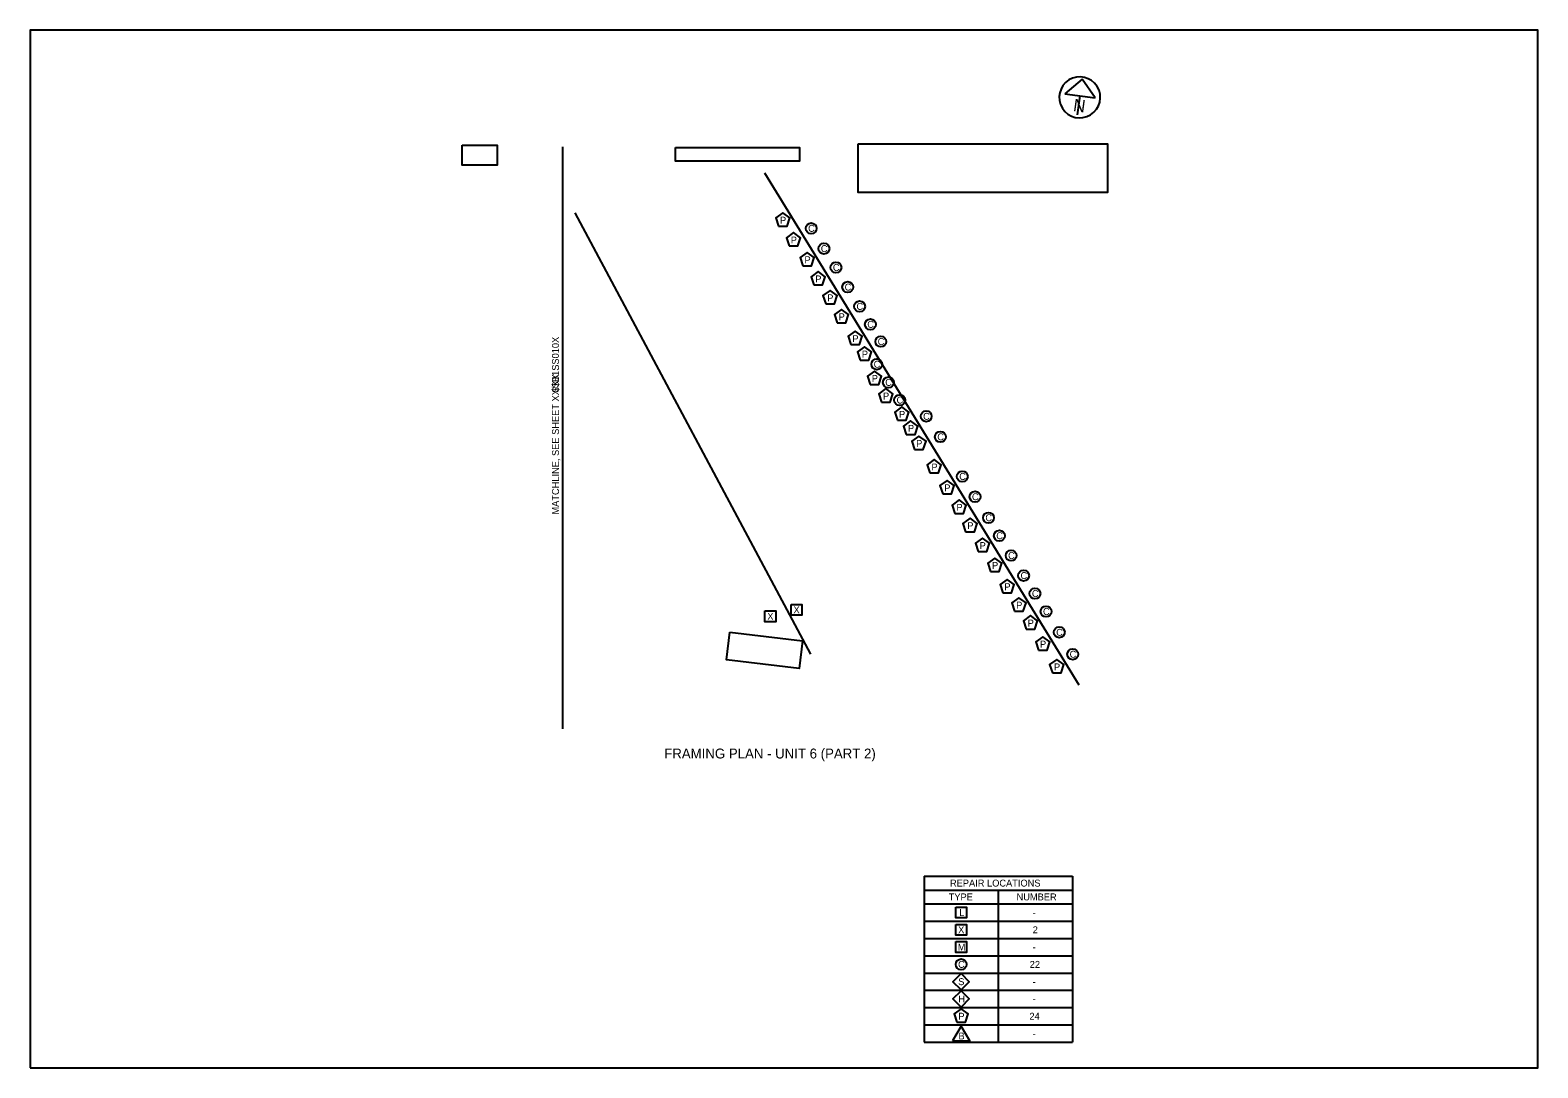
# Model space of a CAD drawing. Extents: x 100 to 130.5, y 100 to 121.
import ezdxf

# ---------------------------------------------------------------- set-up
doc = ezdxf.new("R2010")
doc.units = 0
for name, color, linetype in [('BR_P_Gen_Text', 7, 'Continuous'), ('BR_X_Sub_Centerline', 7, 'Continuous'), ('BR_X_Sub_Text', 7, 'Continuous'), ('SC_Scratch1', 7, 'Continuous'), ('SH_Data', 7, 'Continuous'), ('SH_Masking', 7, 'Continuous')]:
    doc.layers.add(name, color=color, linetype=linetype)

msp = doc.modelspace()

# ---------------------------------------------------------------- linework, layer by layer
at = {"layer": 'BR_P_Gen_Text'}
for p, q in [((110.767, 118.639), (110.767, 106.861)), ((118.083, 103.879), (118.083, 100.519)), ((118.083, 103.879), (121.083, 103.879)), ((121.083, 103.879), (121.083, 100.519)), ((118.083, 103.599), (121.083, 103.599)), ((119.583, 103.599), (119.583, 100.519)), ((118.083, 103.319), (121.083, 103.319)), ((118.083, 102.969), (121.083, 102.969)), ((118.083, 102.619), (121.083, 102.619)), ((118.083, 102.269), (121.083, 102.269)), ((118.083, 101.919), (121.083, 101.919)), ((118.083, 101.569), (121.083, 101.569)), ((118.083, 101.219), (121.083, 101.219)), ((118.083, 100.869), (121.083, 100.869)), ((118.083, 100.519), (121.083, 100.519))]:
    msp.add_line(p, q, dxfattribs=at)
for points in [[(115.136, 117.033), (115.312, 117.033), (115.367, 117.201), (115.224, 117.304), (115.082, 117.201)], [(115.355, 116.632), (115.531, 116.632), (115.586, 116.8), (115.443, 116.903), (115.3, 116.8)], [(115.633, 116.231), (115.809, 116.231), (115.863, 116.399), (115.721, 116.502), (115.578, 116.399)], [(115.851, 115.844), (116.028, 115.844), (116.082, 116.011), (115.939, 116.115), (115.797, 116.011)], [(116.093, 115.461), (116.269, 115.461), (116.323, 115.628), (116.181, 115.732), (116.038, 115.628)], [(116.323, 115.078), (116.5, 115.078), (116.554, 115.246), (116.412, 115.349), (116.269, 115.246)], [(116.601, 114.636), (116.778, 114.636), (116.832, 114.804), (116.689, 114.907), (116.547, 114.804)], [(116.793, 114.322), (116.969, 114.322), (117.023, 114.489), (116.881, 114.593), (116.738, 114.489)], [(116.993, 113.829), (117.169, 113.829), (117.224, 113.997), (117.081, 114.101), (116.939, 113.997)], [(117.221, 113.474), (117.397, 113.474), (117.452, 113.642), (117.309, 113.745), (117.166, 113.642)], [(117.544, 113.105), (117.721, 113.105), (117.775, 113.272), (117.632, 113.376), (117.49, 113.272)], [(117.724, 112.82), (117.901, 112.82), (117.955, 112.988), (117.812, 113.092), (117.67, 112.988)], [(117.892, 112.514), (118.068, 112.514), (118.123, 112.682), (117.98, 112.785), (117.837, 112.682)], [(118.201, 112.038), (118.377, 112.038), (118.432, 112.206), (118.289, 112.309), (118.146, 112.206)], [(118.46, 111.616), (118.636, 111.616), (118.691, 111.783), (118.548, 111.887), (118.405, 111.783)], [(118.707, 111.221), (118.883, 111.221), (118.938, 111.389), (118.795, 111.493), (118.653, 111.389)], [(118.925, 110.85), (119.101, 110.85), (119.156, 111.018), (119.013, 111.122), (118.87, 111.018)], [(119.176, 110.448), (119.352, 110.448), (119.406, 110.616), (119.264, 110.719), (119.121, 110.616)], [(119.426, 110.045), (119.603, 110.045), (119.657, 110.213), (119.514, 110.317), (119.372, 110.213)], [(119.676, 109.615), (119.852, 109.615), (119.907, 109.783), (119.764, 109.886), (119.622, 109.783)], [(119.915, 109.241), (120.091, 109.241), (120.146, 109.409), (120.003, 109.513), (119.861, 109.409)], [(114.863, 109.247), (115.083, 109.247), (115.083, 109.027), (114.863, 109.027)], [(115.393, 109.379), (115.613, 109.379), (115.613, 109.159), (115.393, 109.159)], [(120.148, 108.88), (120.325, 108.88), (120.379, 109.048), (120.237, 109.151), (120.094, 109.048)], [(120.396, 108.454), (120.572, 108.454), (120.627, 108.622), (120.484, 108.725), (120.342, 108.622)], [(120.679, 107.993), (120.855, 107.993), (120.91, 108.161), (120.767, 108.264), (120.624, 108.161)], [(118.723, 103.254), (118.943, 103.254), (118.943, 103.034), (118.723, 103.034)], [(118.723, 102.904), (118.943, 102.904), (118.943, 102.684), (118.723, 102.684)], [(118.723, 102.554), (118.943, 102.554), (118.943, 102.334), (118.723, 102.334)], [(118.833, 101.909), (118.998, 101.744), (118.833, 101.579), (118.668, 101.744)], [(118.833, 101.559), (118.998, 101.394), (118.833, 101.229), (118.668, 101.394)], [(118.745, 100.923), (118.922, 100.923), (118.976, 101.091), (118.833, 101.194), (118.691, 101.091)], [(118.66, 100.544), (119.007, 100.544), (118.833, 100.844)]]:
    msp.add_lwpolyline(points, close=True, dxfattribs=at)
for centre in [(115.8, 116.989), (116.058, 116.579), (116.301, 116.197), (116.54, 115.8), (116.779, 115.409), (116.998, 115.046), (117.208, 114.698), (117.127, 114.239), (117.361, 113.872), (117.59, 113.513), (118.127, 113.185), (118.414, 112.77), (118.857, 111.968), (119.115, 111.557), (119.387, 111.132), (119.607, 110.769), (119.845, 110.368), (120.098, 109.962), (120.327, 109.599), (120.552, 109.235), (120.819, 108.814), (121.091, 108.37), (118.833, 102.094)]:
    msp.add_circle(centre, 0.11, dxfattribs=at)
at = {"layer": 'BR_X_Sub_Centerline'}
for p, q in [((121.22, 107.746), (114.862, 118.106)), ((115.795, 108.373), (111.025, 117.306))]:
    msp.add_line(p, q, dxfattribs=at)
at = {"layer": 'BR_X_Sub_Text'}
for points in [[(113.054, 118.628), (115.565, 118.628), (115.565, 118.347), (113.054, 118.347)], [(114.152, 108.817), (115.625, 108.64), (115.558, 108.081), (114.085, 108.258)]]:
    msp.add_lwpolyline(points, close=True, dxfattribs=at)
at = {"layer": 'SC_Scratch1'}
msp.add_lwpolyline([(100, 100), (130.5, 100), (130.5, 121), (100, 121)], close=True, dxfattribs=at)
at = {"layer": 'SH_Data'}
for p, q in [((121.284, 120.009), (120.932, 119.713)), ((121.542, 119.629), (121.284, 120.009)), ((120.932, 119.713), (121.542, 119.629)), ((121.237, 119.671), (121.184, 119.288))]:
    msp.add_line(p, q, dxfattribs=at)
msp.add_arc((121.233, 119.639), 0.415, 121.8974, 121.8808, dxfattribs=at)
at = {"layer": 'SH_Masking'}
for points in [[(108.741, 118.671), (109.447, 118.671), (109.447, 118.265), (108.741, 118.265)], [(116.753, 118.697), (121.793, 118.697), (121.793, 117.714), (116.753, 117.714)]]:
    msp.add_lwpolyline(points, close=True, dxfattribs=at)

# ---------------------------------------------------------------- texts
at = {"layer": 'BR_P_Gen_Text'}
for s, height, p in [('P', 0.14, (115.168, 117.084)), ('P', 0.14, (115.387, 116.683)), ('C', 0.14, (115.738, 116.919)), ('C', 0.14, (115.995, 116.509)), ('P', 0.14, (115.665, 116.282)), ('C', 0.14, (116.239, 116.127)), ('P', 0.14, (115.883, 115.895)), ('P', 0.14, (116.125, 115.512)), ('C', 0.14, (116.477, 115.73)), ('C', 0.14, (116.716, 115.339)), ('P', 0.14, (116.355, 115.129)), ('C', 0.14, (116.935, 114.976)), ('P', 0.14, (116.633, 114.687)), ('C', 0.14, (117.145, 114.628)), ('P', 0.14, (116.825, 114.373)), ('C', 0.14, (117.064, 114.169)), ('P', 0.14, (117.025, 113.881)), ('C', 0.14, (117.298, 113.802)), ('P', 0.14, (117.253, 113.525)), ('C', 0.14, (117.527, 113.443)), ('P', 0.14, (117.576, 113.156)), ('C', 0.14, (118.064, 113.115)), ('P', 0.14, (117.756, 112.872)), ('P', 0.14, (117.924, 112.565)), ('C', 0.14, (118.351, 112.7)), ('P', 0.14, (118.233, 112.089)), ('C', 0.14, (118.795, 111.898)), ('P', 0.14, (118.492, 111.667)), ('P', 0.14, (118.739, 111.273)), ('C', 0.14, (119.052, 111.487)), ('P', 0.14, (118.957, 110.902)), ('C', 0.14, (119.324, 111.062)), ('C', 0.14, (119.544, 110.699)), ('P', 0.14, (119.207, 110.499)), ('C', 0.14, (119.783, 110.298)), ('P', 0.14, (119.458, 110.097)), ('P', 0.14, (119.708, 109.666)), ('C', 0.14, (120.035, 109.892)), ('C', 0.14, (120.265, 109.529)), ('X', 0.14, (114.912, 109.067)), ('X', 0.14, (115.442, 109.199)), ('P', 0.14, (119.947, 109.293)), ('C', 0.14, (120.489, 109.165)), ('P', 0.14, (120.18, 108.931)), ('C', 0.14, (120.756, 108.744)), ('P', 0.14, (120.428, 108.505)), ('C', 0.14, (121.028, 108.3)), ('P', 0.14, (120.711, 108.044)), ('FRAMING PLAN - UNIT 6 (PART 2)', 0.2, (112.827, 106.261)), ('REPAIR LOCATIONS', 0.14, (118.608, 103.669)), ('TYPE', 0.14, (118.582, 103.389)), ('NUMBER', 0.14, (119.955, 103.389)), ('L', 0.14, (118.795, 103.074)), ('-', 0.14, (120.28, 103.074)), ('X', 0.14, (118.773, 102.724)), ('2', 0.14, (120.281, 102.724)), ('M', 0.14, (118.765, 102.374)), ('-', 0.14, (120.28, 102.374)), ('C', 0.14, (118.771, 102.024)), ('22', 0.14, (120.221, 102.024)), ('S', 0.14, (118.775, 101.674)), ('-', 0.14, (120.28, 101.674)), ('H', 0.14, (118.777, 101.324)), ('-', 0.14, (120.28, 101.324)), ('P', 0.14, (118.777, 100.974)), ('24', 0.14, (120.215, 100.974)), ('B', 0.14, (118.779, 100.574)), ('-', 0.14, (120.28, 100.624))]:
    msp.add_text(s, height=height, dxfattribs=at).set_placement(p)
for s, p in [('$$B1SS010X', (110.697, 113.67)), ('MATCHLINE, SEE SHEET XX/XX', (110.697, 111.197))]:
    msp.add_text(s, height=0.14, rotation=90, dxfattribs=at).set_placement(p)
at = {"layer": 'SH_Data'}
msp.add_text('N', height=0.25, rotation=352.1175, dxfattribs=at).set_placement((121.09, 119.365))

doc.saveas('drawing.dxf')
